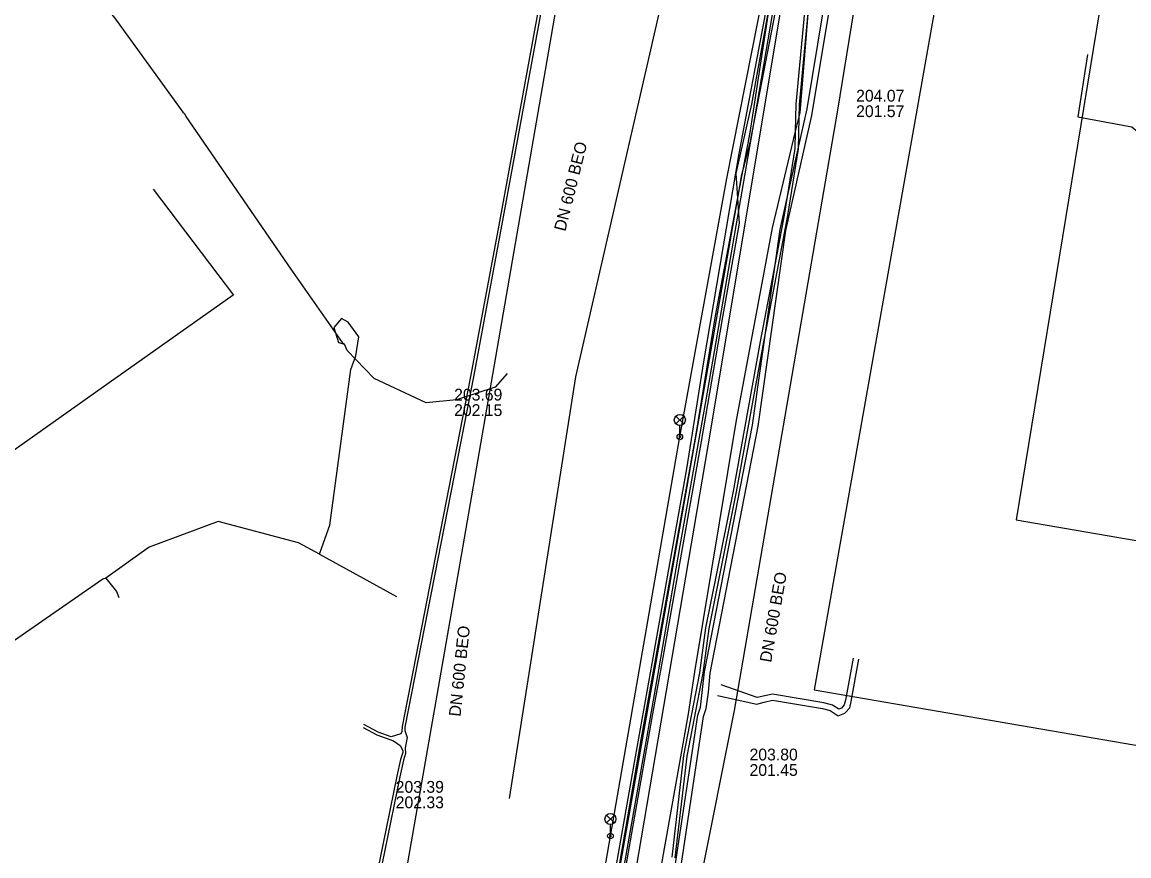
# Model space of a CAD drawing. Extents: x -596228 to -595156, y -1161235 to -1159373.
# Drawn here: x -595916.2 to -595841.1, y -1160145.3 to -1160088.8 of the extents above; entities that cross this region are included whole.
import ezdxf

# ---------------------------------------------------------------- set-up
doc = ezdxf.new("R2010")
doc.units = 0
for name, color, linetype in [('Vrstva 1', 7, 'Continuous'), ('Vrstva 12', 7, 'Continuous'), ('Vrstva 14', 7, 'Continuous'), ('Vrstva 33', 7, 'Continuous'), ('Vrstva 37', 7, 'Continuous'), ('Vrstva 4', 7, 'Continuous'), ('Vrstva 42', 7, 'Continuous'), ('Vrstva 44', 7, 'Continuous'), ('Vrstva 53', 7, 'Continuous'), ('Vrstva 55', 7, 'Continuous')]:
    doc.layers.add(name, color=color, linetype=linetype)

msp = doc.modelspace()

# ---------------------------------------------------------------- linework, layer by layer
at = {"layer": 'Vrstva 1'}
for p, q in [((-595878.63, -1160112.85), (-595863.23, -1160045.57)), ((-595853.63, -1160050.15), (-595860.88, -1160094.77)), ((-595860.88, -1160094.77), (-595867.89, -1160135.48)), ((-595907.31, -1160100.11), (-595901.88, -1160107.3)), ((-595883.15, -1160141.45), (-595878.63, -1160112.85)), ((-595867.89, -1160135.48), (-595876.82, -1160179.87))]:
    msp.add_line(p, q, dxfattribs=at)
msp.add_lwpolyline([(-595901.881, -1160107.299), (-595910.679, -1160113.521), (-595927.4, -1160125.343), (-595937, -1160132.13)], dxfattribs=at)
at = {"layer": 'Vrstva 12'}
for points in [[(-595873.83, -1160048.21), (-595874.58, -1160057.28), (-595878.97, -1160081.97), (-595886.34, -1160124.44), (-595887.99, -1160133.91), (-595889.12, -1160140.39), (-595891.94, -1160156.53), (-595892.78, -1160161.36), (-595893.73, -1160166.74)], [(-595843.91, -1160090.98), (-595844.57, -1160095.21), (-595840.91, -1160095.9), (-595839.39, -1160097.15), (-595840.58, -1160102.86), (-595837.01, -1160107.36), (-595798.93, -1160113.16), (-595779.35, -1160136.8), (-595778.9, -1160137.78)]]:
    msp.add_lwpolyline(points, dxfattribs=at)
at = {"layer": 'Vrstva 14'}
msp.add_lwpolyline([(-595903.525, -1160327.591), (-595903.438, -1160327.11), (-595895.992, -1160276.218), (-595895.362, -1160271.913), (-595894.416, -1160266.829), (-595893.077, -1160257.958), (-595892.847, -1160256.335), (-595887.94, -1160223.167), (-595881.65, -1160186.81), (-595876.814, -1160159.541), (-595869.649, -1160117.522), (-595863.209, -1160078.856), (-595858.091, -1160048.124), (-595857.576, -1160045.207), (-595855.994, -1160045.422), (-595855.543, -1160042.523), (-595857.05, -1160042.292), (-595850.5, -1160006.311), (-595840.026, -1160007.969)], dxfattribs=at)
at = {"layer": 'Vrstva 33'}
for p, q in [((-595871.845, -1160115.505), (-595871.315, -1160116.035)), ((-595871.845, -1160116.035), (-595871.315, -1160115.505)), ((-595871.58, -1160116.92), (-595871.58, -1160116.145)), ((-595876.555, -1160142.575), (-595876.025, -1160143.105)), ((-595876.555, -1160143.105), (-595876.025, -1160142.575)), ((-595876.29, -1160143.99), (-595876.29, -1160143.215))]:
    msp.add_line(p, q, dxfattribs=at)
for centre, radius in [((-595871.58, -1160115.77), 0.375), ((-595871.58, -1160116.92), 0.19), ((-595871.58, -1160116.92), 0.05), ((-595876.29, -1160142.84), 0.375), ((-595876.29, -1160143.99), 0.19), ((-595876.29, -1160143.99), 0.05)]:
    msp.add_circle(centre, radius, dxfattribs=at)
at = {"layer": 'Vrstva 37'}
for points in [[(-595851.153, -1160079.274), (-595852.714, -1160079.02), (-595862.455, -1160134.068), (-595836.577, -1160138.534)], [(-595842.059, -1160081.643), (-595848.753, -1160122.538), (-595834.439, -1160125.011), (-595836.577, -1160138.534)]]:
    msp.add_lwpolyline(points, dxfattribs=at)
at = {"layer": 'Vrstva 42'}
for points in [[(-595852.193, -1160085.121), (-595852.831, -1160085.013), (-595854.297, -1160084.763), (-595855.968, -1160084.478), (-595856.175, -1160084.443), (-595856.826, -1160084.223), (-595859.487, -1160083.326), (-595860.094, -1160083.121), (-595860.498, -1160082.985), (-595862.074, -1160082.453), (-595863.404, -1160082.186), (-595864.175, -1160082.032), (-595878.226, -1160079.213), (-595879.54, -1160080.264), (-595881.238, -1160088.221), (-595883.868, -1160102.562), (-595885.758, -1160112.701), (-595890.428, -1160136.561), (-595890.453, -1160136.9), (-595890.51, -1160137.05)], [(-595875.884, -1160147.461), (-595871.512, -1160122.724), (-595867.647, -1160100.73), (-595867.366, -1160099.13), (-595866.82, -1160096.978), (-595864.056, -1160082.698), (-595863.457, -1160082.87), (-595861.807, -1160083.949), (-595861.622, -1160084.07), (-595860.866, -1160084.442), (-595860.721, -1160084.513), (-595860.668, -1160084.539), (-595860.366, -1160084.688), (-595858.818, -1160085.449), (-595856.567, -1160086.199), (-595854.802, -1160086.398), (-595854.04, -1160086.484), (-595853.812, -1160086.51), (-595853.422, -1160086.457), (-595852.843, -1160086.379), (-595852.408, -1160086.32), (-595852.315, -1160086.307)], [(-595869.636, -1160134.237), (-595869.522, -1160132.94), (-595866.263, -1160116.198), (-595864.385, -1160102.93), (-595862.632, -1160095.129), (-595861.47, -1160088.182), (-595860.478, -1160084.891), (-595860.366, -1160084.688), (-595860.177, -1160084.342), (-595860.174, -1160084.337), (-595860.169, -1160084.339), (-595858.666, -1160085.078), (-595856.48, -1160085.806), (-595855.408, -1160085.927), (-595854.802, -1160086.398), (-595852.407, -1160088.26)], [(-595872.109, -1160145.435), (-595871.299, -1160138.535), (-595870.219, -1160132.924), (-595869.819, -1160129.874), (-595867.948, -1160120.601), (-595866.098, -1160110.442), (-595865.117, -1160105.25), (-595864.479, -1160101.873), (-595864.274, -1160100.607), (-595863.75, -1160097.371), (-595863.723, -1160096.21), (-595863.68, -1160094.364), (-595862.936, -1160086.393)], [(-595862.744, -1160086.487), (-595863.48, -1160094.376), (-595863.501, -1160095.292), (-595863.55, -1160097.378), (-595863.55, -1160097.389), (-595864.281, -1160101.907), (-595865.723, -1160109.536), (-595865.902, -1160110.478), (-595867.752, -1160120.639), (-595869.621, -1160129.906), (-595870.021, -1160132.956), (-595871.101, -1160138.565), (-595871.911, -1160145.465)], [(-595881.042, -1160088.259), (-595883.672, -1160102.598), (-595885.562, -1160112.739), (-595890.232, -1160136.599), (-595890.24, -1160136.844), (-595890.08, -1160137.31), (-595890.219, -1160138.005), (-595890.195, -1160138.391), (-595890.343, -1160138.846), (-595890.582, -1160139.98), (-595892.212, -1160147.938)], [(-595875.49, -1160147.531), (-595873.416, -1160135.703), (-595872.83, -1160132.508), (-595870.109, -1160117.236), (-595868.704, -1160109.049), (-595867.537, -1160102.418), (-595867.647, -1160100.73), (-595867.757, -1160099.046), (-595866.694, -1160094.345), (-595865.55, -1160087.923)], [(-595874.688, -1160156.38), (-595870.992, -1160135.708), (-595870.562, -1160132.862), (-595867.756, -1160115.913), (-595865.294, -1160102.73), (-595863.723, -1160096.21), (-595863.501, -1160095.292), (-595863.415, -1160094.933), (-595862.846, -1160087.963)], [(-595873.494, -1160156.693), (-595870.36, -1160135.801), (-595870.189, -1160135.249), (-595869.914, -1160132.864), (-595866.657, -1160116.132), (-595865.723, -1160109.536), (-595865.117, -1160105.25), (-595864.779, -1160102.862), (-595864.274, -1160100.607), (-595863.55, -1160097.378), (-595862.944, -1160094.674), (-595861.858, -1160088.086)], [(-595869.023, -1160134.452), (-595866.353, -1160135.044), (-595865.862, -1160134.904), (-595865.296, -1160134.787), (-595861.896, -1160135.337), (-595861.39, -1160135.487), (-595860.832, -1160135.831), (-595860.387, -1160135.662), (-595860.056, -1160135.293), (-595859.955, -1160134.857), (-595859.428, -1160131.986)], [(-595859.823, -1160131.921), (-595860.347, -1160134.775), (-595860.422, -1160135.103), (-595860.619, -1160135.322), (-595860.79, -1160135.387), (-595861.226, -1160135.119), (-595861.806, -1160134.947), (-595865.304, -1160134.381), (-595866.337, -1160134.593), (-595868.78, -1160133.735)], [(-595837.329, -1160168.604), (-595838.64, -1160168.248), (-595842.189, -1160167.823), (-595851.48, -1160166.71), (-595868.445, -1160164), (-595869.541, -1160163.825), (-595870.937, -1160163.602), (-595871.268, -1160163.534), (-595872.199, -1160163.341), (-595872.405, -1160163.064), (-595872.577, -1160162.834), (-595872.586, -1160162.768), (-595872.619, -1160162.52), (-595873.058, -1160159.275), (-595873.094, -1160156.721), (-595869.968, -1160135.891), (-595869.795, -1160135.333), (-595869.636, -1160134.237)], [(-595890.51, -1160137.05), (-595891.167, -1160137.269), (-595892.059, -1160136.948), (-595893.02, -1160136.437)], [(-595893.067, -1160136.638), (-595892.141, -1160137.132), (-595891.018, -1160137.535), (-595890.56, -1160137.86)], [(-595890.56, -1160137.86), (-595890.378, -1160138.198), (-595890.385, -1160138.329), (-595890.537, -1160138.794), (-595890.778, -1160139.94), (-595892.408, -1160147.902)]]:
    msp.add_lwpolyline(points, dxfattribs=at)
at = {"layer": 'Vrstva 44'}
for points in [[(-595877.641, -1160157.25), (-595877.206, -1160154.877), (-595875.823, -1160146.872), (-595874.194, -1160137.323), (-595870.493, -1160116.878), (-595869.152, -1160108.721), (-595866.815, -1160096.285), (-595864.579, -1160081.663), (-595862.969, -1160076.234), (-595861.913, -1160073.61), (-595860.434, -1160067.371), (-595860.472, -1160066.199), (-595860.336, -1160065.565), (-595860.108, -1160064.5), (-595859.919, -1160062.97), (-595859.588, -1160060.589), (-595859.432, -1160059.468), (-595859.081, -1160056.226), (-595858.987, -1160055.362), (-595857.892, -1160045.25)], [(-595875.94, -1160146.32), (-595874.58, -1160138.63), (-595873.46, -1160132.3), (-595872.34, -1160126.02), (-595871.1, -1160119.08), (-595869.96, -1160111.84), (-595868.61, -1160103.97), (-595867.55, -1160097.7), (-595865.77, -1160088.25)]]:
    msp.add_lwpolyline(points, dxfattribs=at)
at = {"layer": 'Vrstva 53'}
msp.add_lwpolyline([(-595834.49, -1160024.39), (-595844.31, -1160035.25), (-595847.42, -1160039.55), (-595847.57, -1160039.84), (-595848.73, -1160040.53), (-595850.81, -1160041.8), (-595852.8, -1160043.6), (-595853.34, -1160044.28), (-595853.98, -1160044.54), (-595855.28, -1160044.61), (-595856.08, -1160045.82), (-595856.8, -1160047.16), (-595857.54, -1160049.46), (-595859.63, -1160057.71), (-595861.65, -1160065.98), (-595862.86, -1160074.22), (-595864.25, -1160082.03), (-595866.66, -1160096.08), (-595868.31, -1160105.61), (-595869.84, -1160114.54), (-595871.58, -1160124.29), (-595873.02, -1160132.72), (-595874.46, -1160140.81), (-595876.52, -1160152.45)], dxfattribs=at)
at = {"layer": 'Vrstva 55'}
msp.add_line((-595896.03, -1160124.88), (-595890.8, -1160127.75), dxfattribs=at)
for points in [[(-595953.14, -1160066.86), (-595953.59, -1160065.3), (-595952.99, -1160064.31), (-595945.28, -1160059.37), (-595942.81, -1160058.82), (-595940.24, -1160059.39), (-595938.78, -1160060.75), (-595927.72, -1160074.78), (-595916.43, -1160079.83), (-595912.7, -1160084.91), (-595909.8, -1160088.68), (-595905.31, -1160094.89), (-595905.19, -1160094.98)], [(-595901.722, -1160303.649), (-595901.92, -1160299.12), (-595902.19, -1160291.297), (-595890.66, -1160226.32), (-595886.19, -1160198.97), (-595881.04, -1160171.41), (-595876.29, -1160143.99), (-595871.58, -1160116.92), (-595868.39, -1160099.39), (-595861.162, -1160062.826), (-595862.06, -1160062.41)], [(-595905.19, -1160094.98), (-595905.11, -1160095.19), (-595897.98, -1160105.54), (-595894.49, -1160110.51), (-595894.34, -1160110.64)], [(-595896.03, -1160124.88), (-595895.87, -1160124.42), (-595895.34, -1160122.91), (-595893.91, -1160112.36), (-595893.56, -1160111.42), (-595893.36, -1160110.14), (-595894.08, -1160109.15), (-595894.53, -1160108.9), (-595895.07, -1160109.51), (-595894.75, -1160110.51), (-595894.34, -1160110.64)], [(-595883.3, -1160112.61), (-595884.11, -1160113.55), (-595886.74, -1160114.41), (-595888.8, -1160114.6), (-595892.33, -1160112.95), (-595894.15, -1160111.07), (-595894.34, -1160110.64)], [(-595896.03, -1160124.88), (-595897.45, -1160124.11), (-595902.92, -1160122.65), (-595907.6, -1160124.41), (-595910.53, -1160126.51)], [(-595910.53, -1160126.51), (-595910.74, -1160126.58), (-595920.37, -1160133.24), (-595921.07, -1160132.81), (-595924.98, -1160127.51), (-595925.51, -1160126.57)], [(-595910.53, -1160126.51), (-595909.8, -1160127.4), (-595909.64, -1160127.82)]]:
    msp.add_lwpolyline(points, dxfattribs=at)

# ---------------------------------------------------------------- texts
at = {"layer": 'Vrstva 4'}
for s, p in [('204.07', (-595859.619, -1160094.18)), ('201.57', (-595859.619, -1160095.23)), ('203.69', (-595886.898, -1160114.455)), ('202.15', (-595886.898, -1160115.505)), ('203.80', (-595866.852, -1160138.864)), ('201.45', (-595866.852, -1160139.914)), ('203.39', (-595890.862, -1160141.058)), ('202.33', (-595890.862, -1160142.108))]:
    msp.add_text(s, height=0.8, dxfattribs=at).set_placement(p)
for rotation, p in [(76, (-595879.353, -1160103.021)), (80, (-595865.386, -1160132.257)), (84, (-595886.465, -1160135.919))]:
    msp.add_text('DN 600 BEO', height=0.8, rotation=rotation, dxfattribs=at).set_placement(p)

doc.saveas('drawing.dxf')
